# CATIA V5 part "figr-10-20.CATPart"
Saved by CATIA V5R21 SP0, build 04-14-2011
Part number: Part1
Bounding box of the stored display mesh (mm): x -60 to 60, y -90 to 70, z -46.082 to 16.155
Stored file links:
  D:\CATIA V5R21 E-RESOURCES\CATIA-V5R21\catia-v5r21-prt\c10-catia-v5r20-prt\c10-catia-v5r21-figr-10-20.CATPart
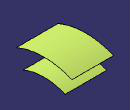
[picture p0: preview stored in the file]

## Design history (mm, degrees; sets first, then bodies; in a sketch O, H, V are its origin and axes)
Set1
  Sketch1 on yz-plane, origin (0, 0, 0), H (0, 1, 0), V (0, 0, 1)
    arc A1 centre (-10, -190) radius 206.1553 from (-90, 0) to (70, 0) cw
  Extrude1: Element1 Sketch1, Lim1 60, Lim2 60, Direction yz-plane
  Offset1: Offset Extrude1, Length 50
Body1 (main body)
